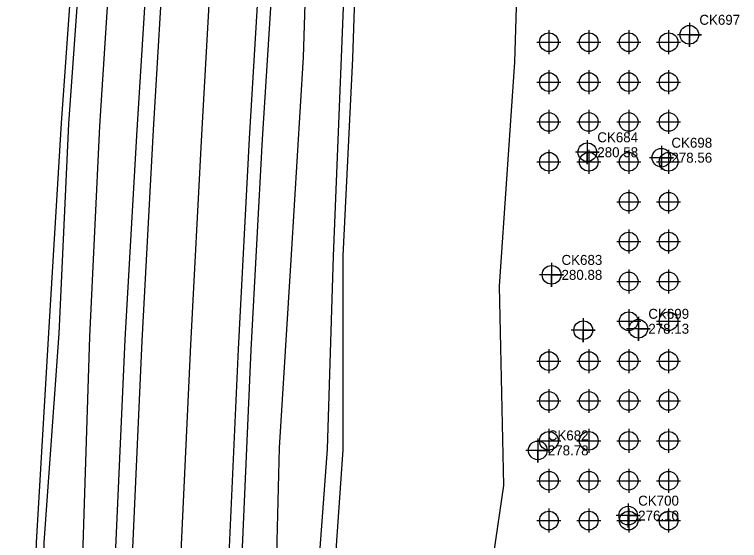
# Model space of a CAD drawing. Extents: x 1941547 to 1942851, y 663002 to 668358.
# Drawn here: x 1941926.1 to 1942107.8, y 667675 to 667807 of the extents above; entities that cross this region are included whole.
import ezdxf

# ---------------------------------------------------------------- set-up
doc = ezdxf.new("R2010")
doc.units = 0
for name, color, linetype in [('CTL GPS Vertical Cogo Elevation', 7, 'Continuous'), ('CTL NGS Vertical CELL', 7, 'Continuous'), ('Exist DTM Drainline Cogo Elevation', 7, 'Continuous'), ('Exist DTM QL2 LIDAR Elevation Point', 7, 'Continuous'), ('Exist Property Iron Pin Cogo Number', 7, 'Continuous'), ('Exist Roads EOP Cogo Point CELL', 7, 'Continuous'), ('Exist Roads EOT', 7, 'Continuous'), ('Exist Utilities Telephone UG Cable SUE LOS C Cogo Elevation', 7, 'Continuous'), ('Exist Utilities Telephone UG FO SUE LOS C Cogo Elevation', 7, 'Continuous')]:
    doc.layers.add(name, color=color, linetype=linetype)

msp = doc.modelspace()

# ---------------------------------------------------------------- linework, layer by layer
at = {"layer": 'CTL NGS Vertical CELL'}
for points in [[(1942024.37, 668012.57), (1942022.28, 667994.37), (1942017.39, 667944.52), (1942014.27, 667895.82), (1942009.92, 667846.63), (1942007.93, 667796.15), (1942005.97, 667746.35), (1942004.4, 667697.91), (1942000.78, 667648.26), (1941999.86, 667599.46), (1941998.39, 667548.71), (1942000.68, 667500.48)], [(1942026.8, 668012.52), (1942024.33, 667994.23), (1942019.53, 667944.62), (1942016.16, 667895.49), (1942012.43, 667846.36), (1942010.79, 667795.94), (1942008.34, 667746.43), (1942008.34, 667697.72), (1942004.96, 667648.49), (1942005.04, 667599.29), (1942003.6, 667548.44), (1942003.59, 667500.58)], [(1941930.54, 667422.84), (1941928.68, 667463.46), (1941928.78, 667514.02), (1941930.06, 667568.07), (1941931.99, 667622.09), (1941933.48, 667674.51), (1941937.26, 667726.95), (1941939.71, 667779.55), (1941943.19, 667828.89), (1941946.38, 667878.43), (1941949.61, 667928.57), (1941952.29, 667965.88), (1941953.97, 667997.88)], [(1941928.41, 667422.42), (1941926.07, 667463.45), (1941926.54, 667514.2), (1941927.95, 667567.47), (1941929.84, 667622.24), (1941931.61, 667674.49), (1941934.69, 667727.1), (1941937.88, 667779.66), (1941941.36, 667829.21), (1941944.43, 667878.58), (1941947.39, 667928.96), (1941950.55, 667966.21)]]:
    msp.add_lwpolyline(points, dxfattribs=at)
at = {"layer": 'Exist DTM Drainline Cogo Elevation'}
for points in [[(1942095.21, 667804.87), (1942095.21, 667798.87), (1942095.21, 667801.87), (1942098.21, 667801.87), (1942092.21, 667801.87)], [(1942095.21, 667804.87), (1942095.21, 667798.87), (1942095.21, 667801.87), (1942098.21, 667801.87), (1942092.21, 667801.87)], [(1942069.63, 667775.4), (1942069.63, 667769.4), (1942069.63, 667772.4), (1942072.63, 667772.4), (1942066.63, 667772.4)], [(1942069.63, 667775.4), (1942069.63, 667769.4), (1942069.63, 667772.4), (1942072.63, 667772.4), (1942066.63, 667772.4)], [(1942088.2, 667774.03), (1942088.2, 667768.03), (1942088.2, 667771.03), (1942091.2, 667771.03), (1942085.2, 667771.03)], [(1942088.2, 667774.03), (1942088.2, 667768.03), (1942088.2, 667771.03), (1942091.2, 667771.03), (1942085.2, 667771.03)], [(1942060.66, 667744.64), (1942060.66, 667738.64), (1942060.66, 667741.64), (1942063.66, 667741.64), (1942057.66, 667741.64)], [(1942060.66, 667744.64), (1942060.66, 667738.64), (1942060.66, 667741.64), (1942063.66, 667741.64), (1942057.66, 667741.64)], [(1942068.61, 667730.76), (1942068.61, 667724.76), (1942068.61, 667727.76), (1942071.61, 667727.76), (1942065.61, 667727.76)], [(1942082.42, 667731.12), (1942082.42, 667725.12), (1942082.42, 667728.12), (1942085.42, 667728.12), (1942079.42, 667728.12)], [(1942082.42, 667731.12), (1942082.42, 667725.12), (1942082.42, 667728.12), (1942085.42, 667728.12), (1942079.42, 667728.12)], [(1942057.22, 667700.61), (1942057.22, 667694.61), (1942057.22, 667697.61), (1942060.22, 667697.61), (1942054.22, 667697.61)], [(1942057.22, 667700.61), (1942057.22, 667694.61), (1942057.22, 667697.61), (1942060.22, 667697.61), (1942054.22, 667697.61)], [(1942079.87, 667684.25), (1942079.87, 667678.25), (1942079.87, 667681.25), (1942082.87, 667681.25), (1942076.87, 667681.25)], [(1942079.87, 667684.25), (1942079.87, 667678.25), (1942079.87, 667681.25), (1942082.87, 667681.25), (1942076.87, 667681.25)]]:
    msp.add_lwpolyline(points, dxfattribs=at)
for centre in [(1942095.21, 667801.87), (1942095.21, 667801.87), (1942069.63, 667772.4), (1942069.63, 667772.4), (1942088.2, 667771.03), (1942088.2, 667771.03), (1942060.66, 667741.64), (1942060.66, 667741.64), (1942068.61, 667727.76), (1942082.42, 667728.12), (1942082.42, 667728.12), (1942057.22, 667697.61), (1942057.22, 667697.61), (1942079.87, 667681.25), (1942079.87, 667681.25)]:
    msp.add_circle(centre, 2.34, dxfattribs=at)
at = {"layer": 'Exist DTM QL2 LIDAR Elevation Point'}
for points in [[(1942060, 667803), (1942060, 667800)], [(1942070, 667803), (1942070, 667800)], [(1942080, 667803), (1942080, 667800)], [(1942090, 667803), (1942090, 667800)], [(1942057, 667800), (1942060, 667800)], [(1942060, 667800), (1942063, 667800)], [(1942060, 667800), (1942060, 667797)], [(1942067, 667800), (1942070, 667800)], [(1942070, 667800), (1942073, 667800)], [(1942070, 667800), (1942070, 667797)], [(1942077, 667800), (1942080, 667800)], [(1942080, 667800), (1942083, 667800)], [(1942080, 667800), (1942080, 667797)], [(1942087, 667800), (1942090, 667800)], [(1942090, 667800), (1942093, 667800)], [(1942090, 667800), (1942090, 667797)], [(1942060, 667793), (1942060, 667790)], [(1942070, 667793), (1942070, 667790)], [(1942080, 667793), (1942080, 667790)], [(1942090, 667793), (1942090, 667790)], [(1942057, 667790), (1942060, 667790)], [(1942060, 667790), (1942063, 667790)], [(1942060, 667790), (1942060, 667787)], [(1942067, 667790), (1942070, 667790)], [(1942070, 667790), (1942073, 667790)], [(1942070, 667790), (1942070, 667787)], [(1942077, 667790), (1942080, 667790)], [(1942080, 667790), (1942083, 667790)], [(1942080, 667790), (1942080, 667787)], [(1942087, 667790), (1942090, 667790)], [(1942090, 667790), (1942093, 667790)], [(1942090, 667790), (1942090, 667787)], [(1942060, 667783), (1942060, 667780)], [(1942070, 667783), (1942070, 667780)], [(1942080, 667783), (1942080, 667780)], [(1942090, 667783), (1942090, 667780)], [(1942057, 667780), (1942060, 667780)], [(1942060, 667780), (1942063, 667780)], [(1942060, 667780), (1942060, 667777)], [(1942067, 667780), (1942070, 667780)], [(1942070, 667780), (1942073, 667780)], [(1942070, 667780), (1942070, 667777)], [(1942077, 667780), (1942080, 667780)], [(1942080, 667780), (1942083, 667780)], [(1942080, 667780), (1942080, 667777)], [(1942087, 667780), (1942090, 667780)], [(1942090, 667780), (1942093, 667780)], [(1942090, 667780), (1942090, 667777)], [(1942060, 667773), (1942060, 667770)], [(1942070, 667773), (1942070, 667770)], [(1942080, 667773), (1942080, 667770)], [(1942090, 667773), (1942090, 667770)], [(1942057, 667770), (1942060, 667770)], [(1942060, 667770), (1942063, 667770)], [(1942060, 667770), (1942060, 667767)], [(1942067, 667770), (1942070, 667770)], [(1942070, 667770), (1942073, 667770)], [(1942070, 667770), (1942070, 667767)], [(1942077, 667770), (1942080, 667770)], [(1942080, 667770), (1942083, 667770)], [(1942080, 667770), (1942080, 667767)], [(1942087, 667770), (1942090, 667770)], [(1942090, 667770), (1942093, 667770)], [(1942090, 667770), (1942090, 667767)], [(1942080, 667763), (1942080, 667760)], [(1942090, 667763), (1942090, 667760)], [(1942077, 667760), (1942080, 667760)], [(1942080, 667760), (1942083, 667760)], [(1942080, 667760), (1942080, 667757)], [(1942087, 667760), (1942090, 667760)], [(1942090, 667760), (1942093, 667760)], [(1942090, 667760), (1942090, 667757)], [(1942080, 667753), (1942080, 667750)], [(1942090, 667753), (1942090, 667750)], [(1942077, 667750), (1942080, 667750)], [(1942080, 667750), (1942083, 667750)], [(1942080, 667750), (1942080, 667747)], [(1942087, 667750), (1942090, 667750)], [(1942090, 667750), (1942093, 667750)], [(1942090, 667750), (1942090, 667747)], [(1942080, 667743), (1942080, 667740)], [(1942090, 667743), (1942090, 667740)], [(1942077, 667740), (1942080, 667740)], [(1942080, 667740), (1942083, 667740)], [(1942080, 667740), (1942080, 667737)], [(1942087, 667740), (1942090, 667740)], [(1942090, 667740), (1942093, 667740)], [(1942090, 667740), (1942090, 667737)], [(1942080, 667733), (1942080, 667730)], [(1942090, 667733), (1942090, 667730)], [(1942077, 667730), (1942080, 667730)], [(1942080, 667730), (1942083, 667730)], [(1942080, 667730), (1942080, 667727)], [(1942087, 667730), (1942090, 667730)], [(1942090, 667730), (1942093, 667730)], [(1942090, 667730), (1942090, 667727)], [(1942060, 667723), (1942060, 667720)], [(1942070, 667723), (1942070, 667720)], [(1942080, 667723), (1942080, 667720)], [(1942090, 667723), (1942090, 667720)], [(1942057, 667720), (1942060, 667720)], [(1942060, 667720), (1942063, 667720)], [(1942060, 667720), (1942060, 667717)], [(1942067, 667720), (1942070, 667720)], [(1942070, 667720), (1942073, 667720)], [(1942070, 667720), (1942070, 667717)], [(1942077, 667720), (1942080, 667720)], [(1942080, 667720), (1942083, 667720)], [(1942080, 667720), (1942080, 667717)], [(1942087, 667720), (1942090, 667720)], [(1942090, 667720), (1942093, 667720)], [(1942090, 667720), (1942090, 667717)], [(1942060, 667713), (1942060, 667710)], [(1942070, 667713), (1942070, 667710)], [(1942080, 667713), (1942080, 667710)], [(1942090, 667713), (1942090, 667710)], [(1942057, 667710), (1942060, 667710)], [(1942060, 667710), (1942063, 667710)], [(1942060, 667710), (1942060, 667707)], [(1942067, 667710), (1942070, 667710)], [(1942070, 667710), (1942073, 667710)], [(1942070, 667710), (1942070, 667707)], [(1942077, 667710), (1942080, 667710)], [(1942080, 667710), (1942083, 667710)], [(1942080, 667710), (1942080, 667707)], [(1942087, 667710), (1942090, 667710)], [(1942090, 667710), (1942093, 667710)], [(1942090, 667710), (1942090, 667707)], [(1942060, 667703), (1942060, 667700)], [(1942070, 667703), (1942070, 667700)], [(1942080, 667703), (1942080, 667700)], [(1942090, 667703), (1942090, 667700)], [(1942057, 667700), (1942060, 667700)], [(1942060, 667700), (1942063, 667700)], [(1942060, 667700), (1942060, 667697)], [(1942067, 667700), (1942070, 667700)], [(1942070, 667700), (1942073, 667700)], [(1942070, 667700), (1942070, 667697)], [(1942077, 667700), (1942080, 667700)], [(1942080, 667700), (1942083, 667700)], [(1942080, 667700), (1942080, 667697)], [(1942087, 667700), (1942090, 667700)], [(1942090, 667700), (1942093, 667700)], [(1942090, 667700), (1942090, 667697)], [(1942060, 667693), (1942060, 667690)], [(1942070, 667693), (1942070, 667690)], [(1942080, 667693), (1942080, 667690)], [(1942090, 667693), (1942090, 667690)], [(1942057, 667690), (1942060, 667690)], [(1942060, 667690), (1942063, 667690)], [(1942060, 667690), (1942060, 667687)], [(1942067, 667690), (1942070, 667690)], [(1942070, 667690), (1942073, 667690)], [(1942070, 667690), (1942070, 667687)], [(1942077, 667690), (1942080, 667690)], [(1942080, 667690), (1942083, 667690)], [(1942080, 667690), (1942080, 667687)], [(1942087, 667690), (1942090, 667690)], [(1942090, 667690), (1942093, 667690)], [(1942090, 667690), (1942090, 667687)], [(1942060, 667683), (1942060, 667680)], [(1942070, 667683), (1942070, 667680)], [(1942080, 667683), (1942080, 667680)], [(1942090, 667683), (1942090, 667680)], [(1942057, 667680), (1942060, 667680)], [(1942060, 667680), (1942063, 667680)], [(1942060, 667680), (1942060, 667677)], [(1942067, 667680), (1942070, 667680)], [(1942070, 667680), (1942073, 667680)], [(1942070, 667680), (1942070, 667677)], [(1942077, 667680), (1942080, 667680)], [(1942080, 667680), (1942083, 667680)], [(1942080, 667680), (1942080, 667677)], [(1942087, 667680), (1942090, 667680)], [(1942090, 667680), (1942093, 667680)], [(1942090, 667680), (1942090, 667677)]]:
    msp.add_lwpolyline(points, dxfattribs=at)
for centre in [(1942060, 667800), (1942070, 667800), (1942080, 667800), (1942090, 667800), (1942060, 667790), (1942070, 667790), (1942080, 667790), (1942090, 667790), (1942060, 667780), (1942070, 667780), (1942080, 667780), (1942090, 667780), (1942060, 667770), (1942070, 667770), (1942080, 667770), (1942090, 667770), (1942080, 667760), (1942090, 667760), (1942080, 667750), (1942090, 667750), (1942080, 667740), (1942090, 667740), (1942080, 667730), (1942090, 667730), (1942060, 667720), (1942070, 667720), (1942080, 667720), (1942090, 667720), (1942060, 667710), (1942070, 667710), (1942080, 667710), (1942090, 667710), (1942060, 667700), (1942070, 667700), (1942080, 667700), (1942090, 667700), (1942060, 667690), (1942070, 667690), (1942080, 667690), (1942090, 667690), (1942060, 667680), (1942070, 667680), (1942080, 667680), (1942090, 667680)]:
    msp.add_circle(centre, 2.34, dxfattribs=at)
at = {"layer": 'Exist Property Iron Pin Cogo Number'}
msp.add_lwpolyline([(1941986.94, 667972.46), (1941983.14, 667925.62), (1941979.11, 667875.72), (1941975.71, 667825.96), (1941972.91, 667776.76), (1941970.2, 667724.07), (1941967.78, 667672.14), (1941966.03, 667619.74), (1941964.82, 667566.56), (1941964.04, 667513.11), (1941963.9, 667463.6), (1941963.98, 667414.3)], dxfattribs=at)
at = {"layer": 'Exist Roads EOT'}
for points in [[(1941951.96, 667414.49), (1941951.82, 667463.66), (1941951.89, 667513.47), (1941952.66, 667567.03), (1941954.12, 667620.18), (1941955.74, 667673.09), (1941958.11, 667725.12), (1941960.9, 667778.05), (1941963.81, 667827.1), (1941967.02, 667877.05), (1941970.92, 667927.07), (1941974.94, 667973.32)], [(1941998.95, 667971.48), (1941994.9, 667924.27), (1941991.1, 667874.21), (1941987.79, 667824.66), (1941984.92, 667775.88), (1941982.17, 667722.97), (1941979.79, 667671.47), (1941977.97, 667618.81), (1941976.79, 667566.11), (1941976.12, 667512.58), (1941975.9, 667463.33), (1941975.97, 667414.74)]]:
    msp.add_lwpolyline(points, dxfattribs=at)
at = {"layer": 'Exist Utilities Telephone UG Cable SUE LOS C Cogo Elevation'}
for points in [[(1941947.52, 667414.49), (1941948.18, 667463.95), (1941948.33, 667513.56), (1941948.74, 667567.19), (1941950.01, 667620.48), (1941951.44, 667673.18), (1941953.79, 667725.44), (1941956.78, 667778.06), (1941959.88, 667827.56), (1941963.38, 667877.42), (1941967.24, 667927.35), (1941971.03, 667973.65)], [(1942002.64, 667971.13), (1941998.56, 667923.93), (1941994.72, 667874.07), (1941991.26, 667824.47), (1941988.15, 667775.69), (1941985.27, 667722.8), (1941983.08, 667671.41), (1941981.48, 667618.83), (1941980.44, 667566), (1941979.8, 667512.63), (1941979.4, 667463.31), (1941979.4, 667414.56)]]:
    msp.add_lwpolyline(points, dxfattribs=at)
at = {"layer": 'Exist Utilities Telephone UG FO SUE LOS C Cogo Elevation'}
for points in [[(1942015.16, 668036.81), (1942013.71, 667994.65), (1942007.92, 667945.04), (1942004.16, 667896), (1942000.03, 667846.93), (1941998.38, 667796.26), (1941995.44, 667746.75), (1941992.37, 667698.24), (1941991.14, 667648.1), (1941991.07, 667599.08), (1941991.51, 667548.12), (1941993.3, 667500.89), (1941997.12, 667495.7), (1942004.5, 667494.55), (1942017.16, 667495.67), (1942033.91, 667493.9), (1942061.43, 667495.96)], [(1941938.12, 667401.41), (1941938.73, 667423.66), (1941941.78, 667464.33), (1941941.12, 667514.11), (1941938.71, 667567.68), (1941940.02, 667621.54), (1941943.32, 667673.83), (1941944.97, 667726.11), (1941947.44, 667778.97), (1941950.62, 667828.46), (1941954.58, 667878.17), (1941957.72, 667928.48), (1941960.86, 667965.38), (1941963.56, 667974.26)], [(1942061.44, 667498.89), (1942036.78, 667507.17), (1942035.13, 667516.78), (1942045.76, 667564.8), (1942041.25, 667609.68), (1942043.79, 667655.13), (1942048.71, 667688.84), (1942047.6, 667738.81), (1942051.48, 667794.98), (1942052.88, 667842.09), (1942055.45, 667881.88)]]:
    msp.add_lwpolyline(points, dxfattribs=at)

# ---------------------------------------------------------------- texts
at = {"layer": 'CTL GPS Vertical Cogo Elevation'}
for s, p in [('CK697', (1942097.71, 667804.37)), ('CK684', (1942072.13, 667774.9)), ('CK698', (1942090.7, 667773.53)), ('CK683', (1942063.16, 667744.14)), ('CK699', (1942084.92, 667730.62)), ('CK682', (1942059.72, 667700.11)), ('CK700', (1942082.37, 667683.75))]:
    msp.add_text(s, height=2.5, dxfattribs=at).set_placement(p)
at = {"layer": 'Exist Roads EOP Cogo Point CELL'}
for s, p in [('280.58', (1942072.13, 667771.15)), ('278.56', (1942090.7, 667769.78)), ('280.88', (1942063.16, 667740.39)), ('278.13', (1942084.92, 667726.87)), ('278.78', (1942059.72, 667696.36)), ('276.10', (1942082.37, 667680))]:
    msp.add_text(s, height=2.5, dxfattribs=at).set_placement(p)

doc.saveas('drawing.dxf')
